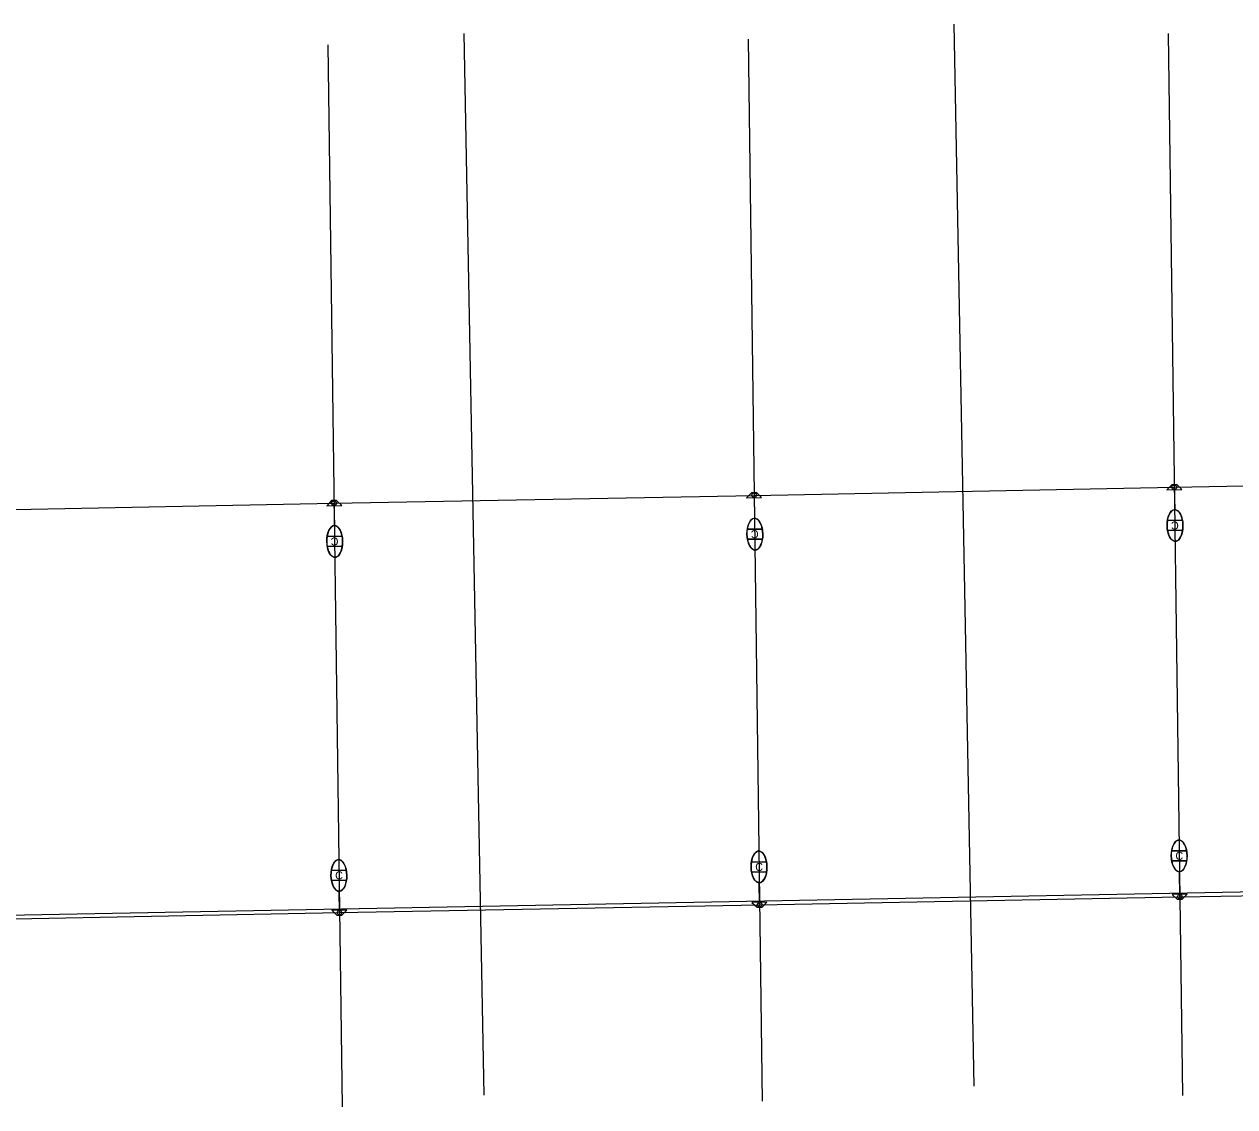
# Model space of a CAD drawing. Extents: x 915723 to 927758, y 636394 to 638609.
# Drawn here: x 922430 to 923035, y 636838 to 637379 of the extents above; entities that cross this region are included whole.
import ezdxf

# ---------------------------------------------------------------- set-up
doc = ezdxf.new("R2010")
doc.units = 0
for name, color, linetype in [('ConduitBM', 7, 'Continuous'), ('DrShaftConc', 7, 'Continuous'), ('Masonry_h', 7, 'Continuous'), ('Miscellaneous2', 7, 'Continuous'), ('PoleLight', 7, 'Continuous'), ('TextStructuresLabel', 7, 'Continuous')]:
    doc.layers.add(name, color=color, linetype=linetype)

msp = doc.modelspace()

# ---------------------------------------------------------------- linework, layer by layer
at = {"layer": 'ConduitBM'}
for p, q in [((922794.92, 637143.96), (923004.89, 637148.06)), ((923004.89, 637148.06), (923214.74, 637151.66)), ((922375.31, 637135.96), (922584.95, 637140.09)), ((922584.95, 637140.09), (922794.92, 637143.96)), ((923007.63, 636943.37), (923218.19, 636946.82)), ((922797.66, 636939.44), (923007.63, 636943.37)), ((922377.73, 636931.52), (922587.7, 636935.51)), ((922587.7, 636935.51), (922797.66, 636939.44))]:
    msp.add_line(p, q, dxfattribs=at)
at = {"layer": 'DrShaftConc'}
for p, q in [((922894.72, 637379.34), (922904.79, 636848.86)), ((922649.76, 637374.68), (922659.84, 636844.21))]:
    msp.add_line(p, q, dxfattribs=at)
msp.add_lwpolyline([(921831.32, 636923.01), (923099.42, 636947.08), (923099.42, 636947.08), (923194.81, 636948.49), (923290.21, 636949.1), (923385.61, 636948.91), (923481.01, 636947.93), (923576.4, 636946.14), (923671.76, 636943.55), (923767.11, 636940.16), (923862.42, 636935.97), (923957.69, 636930.98), (924052.92, 636925.2), (924148.09, 636918.61), (924243.21, 636911.23)], dxfattribs=at)
at = {"layer": 'Masonry_h'}
for p, q in [((922791.87, 637371.82), (922798.98, 636841.29)), ((923001.86, 637374.63), (923008.96, 636844.1)), ((922581.89, 637369.01), (922589, 636838.48))]:
    msp.add_line(p, q, dxfattribs=at)
at = {"layer": 'Miscellaneous2'}
for p, q in [((923008.95, 637131.48), (923001.44, 637131.34)), ((923001.44, 637131.34), (923001.44, 637131.34)), ((922589.02, 637123.5), (922581.51, 637123.35)), ((922581.51, 637123.35), (922581.51, 637123.35)), ((922798.99, 637127.14), (922791.48, 637127)), ((922791.48, 637127), (922791.48, 637127)), ((922791.57, 637122), (922791.57, 637122)), ((922791.57, 637122), (922799.09, 637122.14)), ((923001.54, 637126.34), (923009.05, 637126.48)), ((923001.54, 637126.34), (923001.54, 637126.34)), ((922581.6, 637118.35), (922581.6, 637118.35)), ((922581.6, 637118.35), (922589.12, 637118.5)), ((923011.05, 636966.39), (923003.54, 636966.28)), ((923011.05, 636966.39), (923011.05, 636966.39)), ((922801.06, 636960.88), (922793.54, 636960.74)), ((922801.06, 636960.88), (922801.06, 636960.88)), ((923003.61, 636961.28), (923011.13, 636961.39)), ((923011.13, 636961.39), (923011.13, 636961.39)), ((922591.11, 636956.66), (922583.6, 636956.52)), ((922591.11, 636956.66), (922591.11, 636956.66)), ((922793.64, 636955.74), (922801.15, 636955.88)), ((922801.15, 636955.88), (922801.15, 636955.88)), ((922583.69, 636951.52), (922591.21, 636951.66)), ((922591.21, 636951.66), (922591.21, 636951.66))]:
    msp.add_line(p, q, dxfattribs=at)
for centre, major_axis, start_param, end_param in [((923005.25, 637128.91), (-0.15, 7.92), 1.249648, 1.891946), ((923005.25, 637128.91), (-0.15, 7.92), 4.391271, 5.033538), ((922585.31, 637120.92), (-0.15, 7.92), 1.249648, 1.891946), ((922585.31, 637120.92), (-0.15, 7.92), 4.391271, 5.033538), ((922795.28, 637124.57), (-0.15, 7.92), 1.249648, 1.891946), ((922795.28, 637124.57), (-0.15, 7.92), 4.391271, 5.033538), ((922795.28, 637124.57), (-0.15, 7.92), 4.391241, 4.391271), ((923005.25, 637128.91), (-0.15, 7.92), 4.391241, 4.391271), ((922585.31, 637120.92), (-0.15, 7.92), 4.391241, 4.391271), ((923007.33, 636963.84), (0.12, -7.92), 4.391271, 5.033538), ((923007.33, 636963.84), (0.12, -7.92), 4.391241, 4.391271), ((923007.33, 636963.84), (0.12, -7.92), 1.249648, 1.891946), ((922797.35, 636958.31), (0.15, -7.92), 4.391271, 5.033538), ((922797.35, 636958.31), (0.15, -7.92), 4.391241, 4.391271), ((922797.35, 636958.31), (0.15, -7.92), 1.249648, 1.891946), ((922587.4, 636954.09), (0.15, -7.92), 4.391271, 5.033538), ((922587.4, 636954.09), (0.15, -7.92), 4.391241, 4.391271), ((922587.4, 636954.09), (0.15, -7.92), 1.249648, 1.891946)]:
    msp.add_ellipse(centre, major_axis=major_axis, ratio=0.5, start_param=start_param, end_param=end_param, dxfattribs=at)
at = {"layer": 'PoleLight'}
for p, q in [((923004.88, 637148.11), (923005.09, 637136.83)), ((922584.95, 637140.25), (922585.16, 637128.84)), ((922794.91, 637144.04), (922795.13, 637132.49)), ((923001.44, 637131.34), (923008.95, 637131.48)), ((922581.51, 637123.35), (922589.02, 637123.5)), ((922791.48, 637127), (922798.99, 637127.14)), ((922799.09, 637122.14), (922791.57, 637122)), ((923009.05, 637126.48), (923001.54, 637126.34)), ((922589.12, 637118.5), (922581.6, 637118.35)), ((923003.54, 636966.28), (923011.05, 636966.39)), ((922793.54, 636960.74), (922801.06, 636960.88)), ((923011.13, 636961.39), (923003.61, 636961.28)), ((922583.6, 636956.52), (922591.11, 636956.66)), ((922801.15, 636955.88), (922793.64, 636955.74)), ((923007.63, 636943.54), (923007.45, 636955.92)), ((922591.21, 636951.66), (922583.69, 636951.52)), ((922797.66, 636939.48), (922797.49, 636950.92)), ((922587.75, 636935.48), (922587.55, 636946.17))]:
    msp.add_line(p, q, dxfattribs=at)
for points in [[(923006.1, 637149.32), (923003.6, 637149.26), (923001.15, 637146.72), (923008.64, 637146.87)], [(922586.27, 637141.35), (922583.77, 637141.3), (922581.32, 637138.76), (922588.82, 637138.9)], [(922796.02, 637145.33), (922793.52, 637145.28), (922791.07, 637142.74), (922798.57, 637142.88)], [(922796.37, 636938.16), (922798.87, 636938.22), (922801.32, 636940.76), (922793.82, 636940.61)], [(923006.33, 636942.15), (923008.83, 636942.2), (923011.28, 636944.74), (923003.78, 636944.6)], [(922586.4, 636934.18), (922588.9, 636934.23), (922591.35, 636936.77), (922583.85, 636936.63)]]:
    msp.add_lwpolyline(points, close=True, dxfattribs=at)
for centre in [(923004.88, 637148.07), (922584.95, 637140.08), (922794.92, 637144.06), (922797.66, 636939.46), (923007.63, 636943.44), (922587.7, 636935.47)]:
    msp.add_circle(centre, 1.14, dxfattribs=at)
for centre, major_axis in [((923005.25, 637128.91), (-0.15, 7.92)), ((922585.31, 637120.92), (-0.15, 7.92)), ((922795.28, 637124.57), (-0.15, 7.92)), ((923007.33, 636963.84), (0.12, -7.92)), ((922797.35, 636958.31), (0.15, -7.92)), ((922587.4, 636954.09), (0.15, -7.92))]:
    msp.add_ellipse(centre, major_axis=major_axis, ratio=0.5, dxfattribs=at)
for centre, major_axis, start_param, end_param in [((923005.25, 637128.91), (-0.15, 7.92), 0.847605, 1.249648), ((923005.25, 637128.91), (-0.15, 7.92), 0, 0.847605), ((923005.25, 637128.91), (-0.15, 7.92), 5.033538, 6.283185), ((922585.31, 637120.92), (-0.15, 7.92), 0, 0.847605), ((922585.31, 637120.92), (-0.15, 7.92), 5.033538, 6.283185), ((922795.28, 637124.57), (-0.15, 7.92), 0.847605, 1.249648), ((922795.28, 637124.57), (-0.15, 7.92), 0, 0.847605), ((922795.28, 637124.57), (-0.15, 7.92), 5.033538, 6.283185), ((922585.31, 637120.92), (-0.15, 7.92), 0.847605, 1.249648), ((922795.28, 637124.57), (-0.15, 7.92), 1.891945, 4.391241), ((923005.25, 637128.91), (-0.15, 7.92), 1.891945, 4.391241), ((922585.31, 637120.92), (-0.15, 7.92), 1.891945, 4.391241), ((923007.33, 636963.84), (0.12, -7.92), 1.891945, 4.391241), ((922797.35, 636958.31), (0.15, -7.92), 1.891945, 4.391241), ((922587.4, 636954.09), (0.15, -7.92), 1.891945, 4.391241), ((923007.33, 636963.84), (0.12, -7.92), 5.033538, 6.283185), ((923007.33, 636963.84), (0.12, -7.92), 0, 0.847605), ((923007.33, 636963.84), (0.12, -7.92), 0.847605, 1.249648), ((922797.35, 636958.31), (0.15, -7.92), 5.033538, 6.283185), ((922797.35, 636958.31), (0.15, -7.92), 0, 0.847605), ((922797.35, 636958.31), (0.15, -7.92), 0.847605, 1.249648), ((922587.4, 636954.09), (0.15, -7.92), 5.033538, 6.283185), ((922587.4, 636954.09), (0.15, -7.92), 0, 0.847605), ((922587.4, 636954.09), (0.15, -7.92), 0.847605, 1.249648)]:
    msp.add_ellipse(centre, major_axis=major_axis, ratio=0.5, start_param=start_param, end_param=end_param, dxfattribs=at)

# ---------------------------------------------------------------- texts
at = {"layer": 'TextStructuresLabel'}
for rotation, p in [(181.08772, (923007.08, 637130.94)), (181.08772, (922587.15, 637122.96)), (181.08772, (922797.12, 637126.61)), (0.84473, (923005.49, 636961.81)), (1.08772, (922795.51, 636956.27)), (1.08772, (922585.57, 636952.05))]:
    msp.add_text('C', height=4, rotation=rotation, dxfattribs=at).set_placement(p)

doc.saveas('drawing.dxf')
